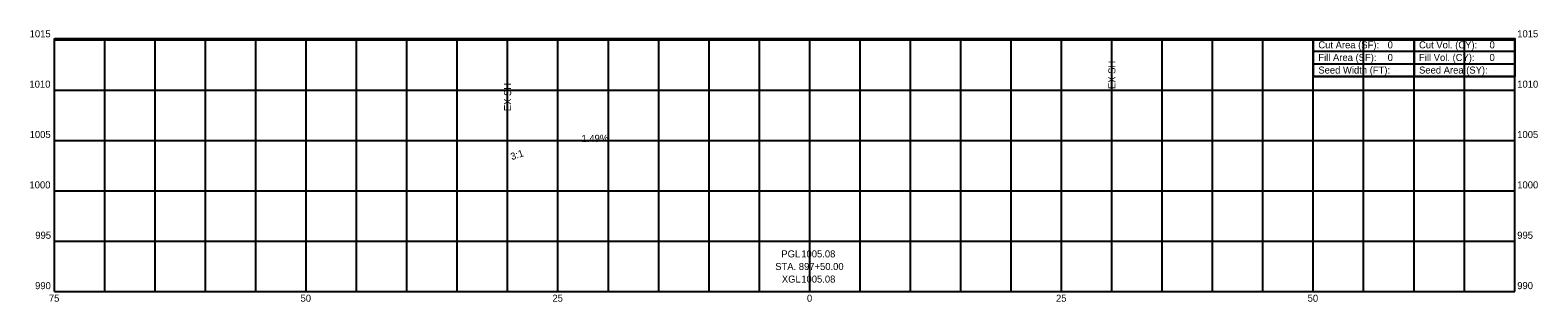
# Model space of a CAD drawing. Extents: x -77 to 72, y 989 to 1016.
import ezdxf

# ---------------------------------------------------------------- set-up
doc = ezdxf.new("R2010")
doc.units = 0
for name, color, linetype in [('Default', 7, 'Continuous'), ('RW_X_CL_100_Curve_Data', 7, 'Continuous'), ('SH_Data', 7, 'Continuous'), ('SH_Major_Grid_Line', 7, 'Continuous'), ('SH_Masking', 7, 'Continuous'), ('SH_Text', 7, 'Continuous')]:
    doc.layers.add(name, color=color, linetype=linetype)

msp = doc.modelspace()

# ---------------------------------------------------------------- linework, layer by layer
at = {"layer": 'Default'}
msp.add_circle((70, 1015.12), 0.000417, dxfattribs=at)
msp.add_circle((70, 1015.12), 0.000417, dxfattribs=at)
msp.add_circle((70, 1015.12), 0.000417, dxfattribs=at)
msp.add_circle((70, 1015.12), 0.000417, dxfattribs=at)
msp.add_circle((70, 1015.12), 0.000417, dxfattribs=at)
msp.add_circle((70, 1015.12), 0.000417, dxfattribs=at)
msp.add_circle((70, 1015.12), 0.000417, dxfattribs=at)
msp.add_circle((70, 1015.12), 0.000417, dxfattribs=at)
msp.add_circle((70, 1015.12), 0.000417, dxfattribs=at)
msp.add_circle((70, 1015.12), 0.000417, dxfattribs=at)
msp.add_circle((70, 1015.12), 0.000417, dxfattribs=at)
msp.add_circle((70, 1015.12), 0.000417, dxfattribs=at)
at = {"layer": 'RW_X_CL_100_Curve_Data'}
for p, q in [((30, 1004.76), (30, 1009.76)), ((-30, 1002.57), (-30, 1007.57))]:
    msp.add_line(p, q, dxfattribs=at)
at = {"layer": 'SH_Data'}
for p, q in [((50, 1015.12), (70, 1015.12)), ((50, 1015.12), (50, 1012.62)), ((60, 1015.12), (60, 1011.37)), ((70, 1015.12), (70, 1012.62)), ((50, 1013.87), (70, 1013.87)), ((50, 1012.62), (70, 1012.62)), ((58.3, 1012), (58.3, 1012)), ((67.95, 1012), (67.95, 1012))]:
    msp.add_line(p, q, dxfattribs=at)
msp.add_lwpolyline([(50, 1012.62), (50, 1011.37), (70, 1011.37), (70, 1012.62)], dxfattribs=at)
at = {"layer": 'SH_Major_Grid_Line'}
for p, q in [((-75, 1015.12), (70, 1015.12)), ((-75, 990), (-75, 1015.12)), ((-70, 990), (-70, 1015.12)), ((-65, 990), (-65, 1015.12)), ((-60, 990), (-60, 1015.12)), ((-55, 990), (-55, 1015.12)), ((-50, 990), (-50, 1015.12)), ((-45, 990), (-45, 1015.12)), ((-40, 990), (-40, 1015.12)), ((-35, 990), (-35, 1015.12)), ((-30, 990), (-30, 1015.12)), ((-25, 990), (-25, 1015.12)), ((-20, 990), (-20, 1015.12)), ((-15, 990), (-15, 1015.12)), ((-10, 990), (-10, 1015.12)), ((-5, 990), (-5, 1015.12)), ((0, 990), (0, 1015.12)), ((5, 990), (5, 1015.12)), ((10, 990), (10, 1015.12)), ((15, 990), (15, 1015.12)), ((20, 990), (20, 1015.12)), ((25, 990), (25, 1015.12)), ((30, 990), (30, 1015.12)), ((35, 990), (35, 1015.12)), ((40, 990), (40, 1015.12)), ((45, 990), (45, 1015.12)), ((50, 990), (50, 1015.12)), ((55, 990), (55, 1015.12)), ((60, 990), (60, 1015.12)), ((65, 990), (65, 1015.12)), ((70, 990), (70, 1015.12)), ((-75, 1015), (70, 1015)), ((-75, 1010), (70, 1010)), ((-75, 1005), (70, 1005)), ((-75, 1000), (70, 1000)), ((-75, 995), (70, 995)), ((-75, 990), (70, 990))]:
    msp.add_line(p, q, dxfattribs=at)
at = {"layer": 'SH_Masking'}
msp.add_lwpolyline([(50, 1015.12), (70, 1015.12), (70, 1011.37), (50, 1011.37)], close=True, dxfattribs=at)

# ---------------------------------------------------------------- texts
at = {"layer": 'RW_X_CL_100_Curve_Data'}
for p in [(30.35, 1010.11), (-29.65, 1007.92)]:
    msp.add_text('EX SH', height=0.7, rotation=90, dxfattribs=at).set_placement(p)
at = {"layer": 'SH_Text'}
for s, p in [('1015', (-77.46, 1015.25)), ('1015', (70.25, 1015.25)), ('Cut Area (SF):', (50.5, 1014.15)), ('Fill Area (SF):', (50.5, 1012.9)), ('0', (57.38, 1014.15)), ('0', (57.38, 1012.9)), ('Cut Vol. (CY):', (60.5, 1014.15)), ('Fill Vol. (CY):', (60.5, 1012.9)), ('0', (67.5, 1014.15)), ('0', (67.5, 1012.9)), ('Seed Width (FT):', (50.5, 1011.65)), ('Seed Area (SY):', (60.5, 1011.65)), ('1010', (-77.48, 1010.25)), ('1010', (70.25, 1010.25)), ('1005', (-77.46, 1005.25)), ('1005', (70.25, 1005.25)), ('1000', (-77.48, 1000.25)), ('1000', (70.25, 1000.25)), ('995', (-76.9, 995.25)), ('995', (70.25, 995.25)), ('PGL ', (-2.82, 993.4)), ('1005.08', (-0.84, 993.4)), ('STA. 897+50.00', (-3.43, 992.15)), ('XGL ', (-2.77, 990.9)), ('1005.08', (-0.84, 990.9)), ('990', (-76.92, 990.25)), ('75', (-75.55, 989)), ('50', (-50.56, 989)), ('25', (-25.55, 989)), ('0', (-0.28, 989)), ('25', (24.45, 989)), ('50', (49.44, 989)), ('990', (70.25, 990.25))]:
    msp.add_text(s, height=0.7, dxfattribs=at).set_placement(p)
for s, rotation, p in [('1.49%', 0.8524, (-22.66, 1004.85)), ('3:1', 18.4328, (-29.58, 1003.05))]:
    msp.add_text(s, height=0.7, rotation=rotation, dxfattribs=at).set_placement(p)

doc.saveas('drawing.dxf')
